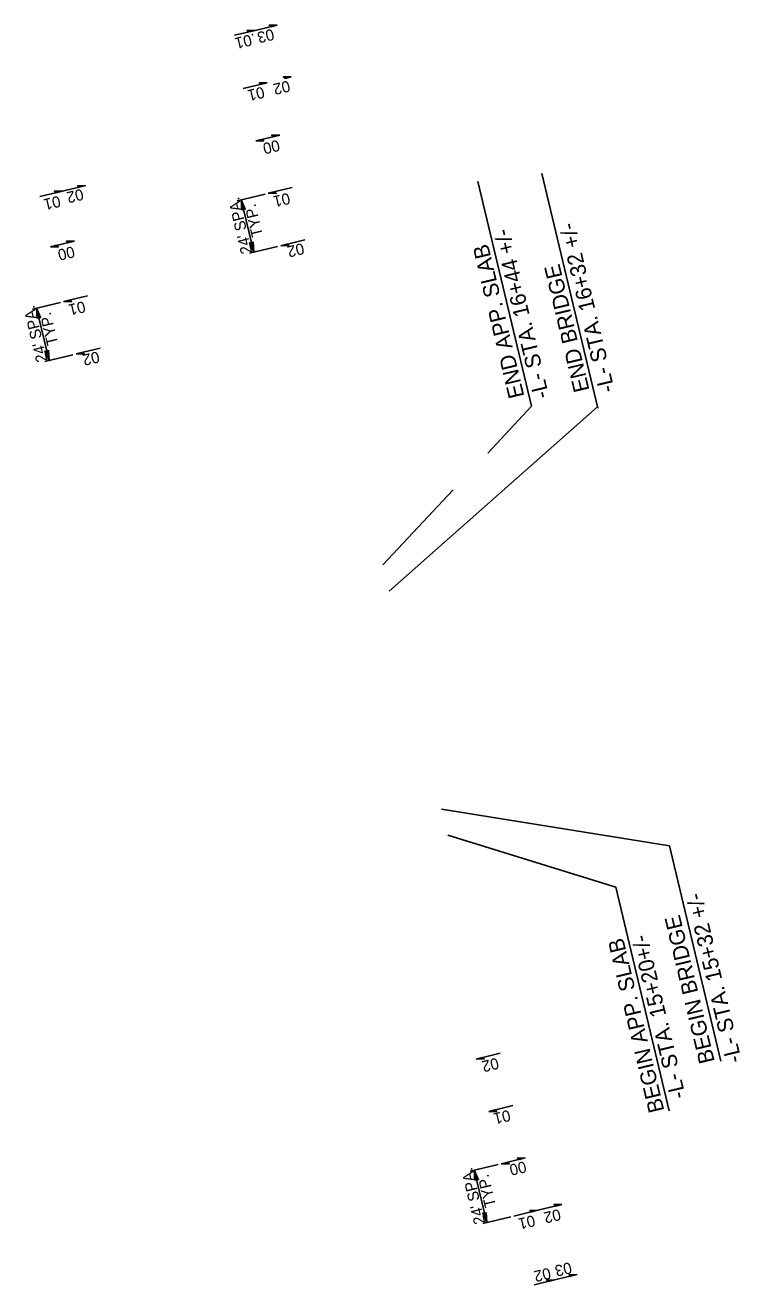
# Model space of a CAD drawing. Extents: x 1735795 to 1737428, y 699740 to 701024.
# Drawn here: x 1737110 to 1737428, y 700462 to 701024 of the extents above; entities that cross this region are included whole.
import ezdxf

# ---------------------------------------------------------------- set-up
doc = ezdxf.new("R2010")
doc.units = 0
for name, color, linetype in [('Prop DSN Text', 7, 'Continuous'), ('Prop Leader Line Medium', 7, 'Continuous'), ('Prop Superelevation  Arrow CELL', 7, 'Continuous'), ('Prop Terminator CELL', 7, 'Continuous')]:
    doc.layers.add(name, color=color, linetype=linetype)

msp = doc.modelspace()

# ---------------------------------------------------------------- linework, layer by layer
at = {"layer": 'Prop Leader Line Medium'}
for p, q in [((1737335.64, 700853.77), (1737311.72, 700954.01)), ((1737365.2, 700852.93), (1737340.24, 700957.54)), ((1737272.13, 700771.42), (1737365.05, 700853.56)), ((1737316.08, 700832.92), (1737335.64, 700853.77)), ((1737269.33, 700783.09), (1737300.68, 700816.51)), ((1737397.09, 700657.85), (1737295.48, 700674.19)), ((1737373.19, 700639.42), (1737298.28, 700662.52)), ((1737420, 700561.83), (1737397.09, 700657.85)), ((1737396.99, 700539.68), (1737373.19, 700639.42))]:
    msp.add_line(p, q, dxfattribs=at)
at = {"layer": 'Prop Superelevation  Arrow CELL'}
for p, q in [((1737212.39, 701021.37), (1737203.18, 701019.19)), ((1737212.39, 701021.37), (1737222.22, 701023.71)), ((1737217.8, 700998.07), (1737207.09, 700995.53)), ((1737223.33, 700974.65), (1737212.63, 700972.1)), ((1737136.84, 700952.18), (1737126.48, 700949.69)), ((1737126.48, 700949.69), (1737116.37, 700947.28)), ((1737216.82, 700948.4), (1737204.34, 700945.4)), ((1737228.93, 700951.31), (1737218.23, 700948.74)), ((1737206.17, 700945.84), (1737211.78, 700922.51)), ((1737131.82, 700927.43), (1737121.12, 700924.88)), ((1737222.42, 700925.06), (1737209.94, 700922.07)), ((1737234.53, 700927.97), (1737223.83, 700925.4)), ((1737137.68, 700903.02), (1737126.98, 700900.45)), ((1737125.57, 700900.11), (1737113.09, 700897.11)), ((1737114.93, 700897.55), (1737120.53, 700874.22)), ((1737143.28, 700879.68), (1737132.59, 700877.11)), ((1737131.18, 700876.77), (1737118.69, 700873.77)), ((1737321.64, 700565.29), (1737310.94, 700562.72)), ((1737327.24, 700541.95), (1737316.55, 700539.38)), ((1737320.74, 700515.7), (1737308.26, 700512.71)), ((1737332.85, 700518.61), (1737322.15, 700516.04)), ((1737310.09, 700513.15), (1737315.7, 700489.81)), ((1737349.15, 700497.84), (1737338.45, 700495.28)), ((1737326.34, 700492.37), (1737313.86, 700489.37)), ((1737338.45, 700495.28), (1737327.76, 700492.71)), ((1737345.91, 700464.23), (1737336.76, 700462.07)), ((1737345.91, 700464.23), (1737355.9, 700466.6))]:
    msp.add_line(p, q, dxfattribs=at)
for points in [[(1737212.39, 701021.37), (1737208.79, 701021.35), (1737209.51, 701020.69)], [(1737222.22, 701023.71), (1737218.63, 701023.68), (1737219.35, 701023.03)], [(1737217.8, 700998.07), (1737214.21, 700998.04), (1737214.93, 700997.39)], [(1737228.49, 701000.63), (1737224.9, 701000.61), (1737225.62, 700999.95)], [(1737223.33, 700974.65), (1737219.74, 700974.62), (1737220.46, 700973.97)], [(1737212.63, 700972.1), (1737216.22, 700972.12), (1737215.5, 700972.78)], [(1737136.84, 700952.18), (1737133.25, 700952.15), (1737133.96, 700951.5)], [(1737126.48, 700949.69), (1737122.89, 700949.66), (1737123.61, 700949.01)], [(1737218.23, 700948.74), (1737221.82, 700948.77), (1737221.1, 700949.42)], [(1737121.12, 700924.88), (1737124.71, 700924.91), (1737123.99, 700925.56)], [(1737131.82, 700927.43), (1737128.23, 700927.4), (1737128.95, 700926.75)], [(1737223.83, 700925.4), (1737227.42, 700925.43), (1737226.7, 700926.08)], [(1737126.98, 700900.45), (1737130.57, 700900.48), (1737129.85, 700901.13)], [(1737132.59, 700877.11), (1737136.18, 700877.14), (1737135.46, 700877.79)], [(1737310.94, 700562.72), (1737314.53, 700562.75), (1737313.81, 700563.4)], [(1737316.55, 700539.38), (1737320.14, 700539.41), (1737319.42, 700540.06)], [(1737322.15, 700516.04), (1737325.74, 700516.07), (1737325.02, 700516.72)], [(1737332.85, 700518.61), (1737329.26, 700518.58), (1737329.98, 700517.93)], [(1737349.15, 700497.84), (1737345.56, 700497.82), (1737346.28, 700497.16)], [(1737338.45, 700495.28), (1737334.86, 700495.25), (1737335.58, 700494.6)], [(1737345.91, 700464.23), (1737342.32, 700464.2), (1737343.04, 700463.55)], [(1737355.9, 700466.6), (1737352.31, 700466.58), (1737353.03, 700465.92)]]:
    msp.add_lwpolyline(points, close=True, dxfattribs=at)
at = {"layer": 'Prop Terminator CELL'}
for points in [[(1737206.47, 700941.29), (1737206.17, 700945.84), (1737208.01, 700941.63), (1737207.1, 700942)], [(1737211.48, 700927.06), (1737211.78, 700922.51), (1737209.94, 700926.72), (1737210.86, 700926.35)], [(1737115.23, 700893), (1737114.93, 700897.55), (1737116.76, 700893.34), (1737115.85, 700893.71)], [(1737120.24, 700878.77), (1737120.53, 700874.22), (1737118.7, 700878.43), (1737119.61, 700878.06)], [(1737310.39, 700508.59), (1737310.09, 700513.15), (1737311.93, 700508.94), (1737311.02, 700509.31)], [(1737315.4, 700494.37), (1737315.7, 700489.81), (1737313.86, 700494.02), (1737314.78, 700493.65)]]:
    msp.add_lwpolyline(points, close=True, dxfattribs=at)

# ---------------------------------------------------------------- texts
at = {"layer": 'Prop DSN Text'}
for s, p in [('-L- STA. 16+44 +/-', (1737343.54, 700858.05)), ('-L- STA. 16+32 +/-', (1737372.76, 700860.74)), ('END APP. SLAB', (1737332.46, 700858.25)), ('END BRIDGE', (1737361.51, 700860.99)), ('-L- STA. 15+32 +/-', (1737429.37, 700561.89)), ('BEGIN BRIDGE', (1737417.34, 700561.64)), ('BEGIN APP. SLAB', (1737394.87, 700539.73)), ('-L- STA. 15+20+/-', (1737404.45, 700545.81))]:
    msp.add_text(s, height=7, rotation=103.4195, dxfattribs=at).set_placement(p)
at = {"layer": 'Prop Superelevation  Arrow CELL'}
for s, rotation, p in [('.01', 193.3409, (1737212.02, 701020.05)), ('03', 193.3409, (1737220.17, 701022.16)), ('02', 193.3409, (1737227.28, 700999.11)), ('01', 193.3409, (1737215.89, 700996.37)), ('00', 193.3409, (1737222.68, 700972.65)), ('01', 193.3409, (1737124.96, 700947.74)), ('02', 193.3409, (1737135.2, 700950.85)), ("24' SPA.", 103.3409, (1737211.09, 700922.34)), ('01', 193.3409, (1737227.28, 700949.04)), ('TYP.', 103.3409, (1737215.89, 700929.95)), ('00', 193.3409, (1737131.25, 700925.22)), ('02', 193.3409, (1737233.56, 700926.66)), ("24' SPA.", 103.3409, (1737119.84, 700874.05)), ('01', 193.3409, (1737136.04, 700900.75)), ('TYP.', 103.3409, (1737124.64, 700881.65)), ('02', 193.3409, (1737142.31, 700878.37)), ('02', 193.3409, (1737320.33, 700563.38)), ('01', 193.3409, (1737325.54, 700540.13)), ("24' SPA.", 103.3409, (1737315.01, 700489.65)), ('00', 193.3409, (1737332.62, 700517.24)), ('TYP.', 103.3409, (1737319.81, 700497.25)), ('01', 193.3409, (1737336.55, 700493.21)), ('02', 193.3409, (1737347.95, 700495.94)), ('02', 193.3409, (1737343.53, 700469.78)), ('03', 193.3409, (1737352.85, 700472.23))]:
    msp.add_text(s, height=5, rotation=rotation, dxfattribs=at).set_placement(p)

doc.saveas('drawing.dxf')
